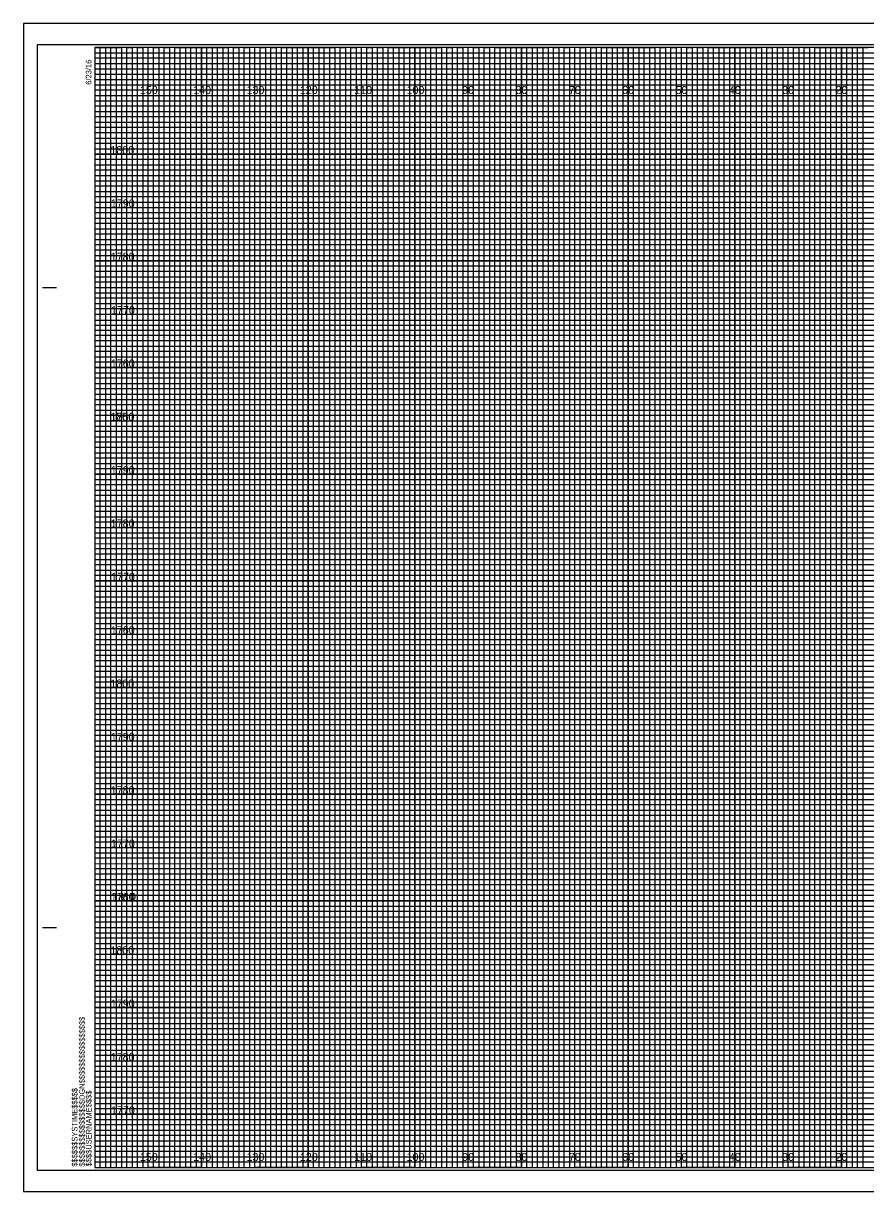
# Model space of a CAD drawing. Extents: x -13 to 323, y -5 to 874.
# Drawn here: x -13.4 to 144.5, y 435.5 to 654.5 of the extents above; entities that cross this region are included whole.
import ezdxf

# ---------------------------------------------------------------- set-up
doc = ezdxf.new("R2010")
doc.units = 0
for name, color, linetype in [('Prop XS Earthwork Shape', 7, 'Continuous'), ('Raster_Level_0', 7, 'Continuous'), ('Scratch_Level_1', 7, 'Continuous'), ('Scratch_Level_3', 7, 'Continuous'), ('Sheet Cross Section CELL', 7, 'Continuous'), ('Sheet Cross Section Grid Minor 1 CELL', 7, 'Continuous'), ('Sheet Cross Section Grid Minor 2 CELL', 7, 'Continuous'), ('Sheet Cutting Line CELL', 7, 'Continuous'), ('Sheet DOT Grid CELL', 7, 'Continuous'), ('Sheet Plot Border Inside CELL', 7, 'Continuous'), ('Sheet Plot Border Outside CELL', 7, 'Continuous')]:
    doc.layers.add(name, color=color, linetype=linetype)

msp = doc.modelspace()

# ---------------------------------------------------------------- linework, layer by layer
at = {"layer": 'Prop XS Earthwork Shape'}
for points in [[(0, 650), (5, 650), (5, 440), (15, 440), (15, 650), (25, 650), (25, 440), (35, 440), (35, 650), (45, 650), (45, 440), (55, 440), (55, 650), (65, 650), (65, 440), (75, 440), (75, 650), (85, 650), (85, 440), (95, 440), (95, 650), (105, 650), (105, 440), (115, 440), (115, 650), (125, 650), (125, 440), (135, 440), (135, 650), (145, 650)], [(0, 645), (275, 645)], [(0, 625), (320, 625), (320, 635), (0, 635)], [(0, 605), (320, 605), (320, 615), (0, 615)], [(0, 585), (320, 585), (320, 595), (0, 595)], [(0, 565), (320, 565), (320, 575), (0, 575)], [(0, 545), (320, 545), (320, 555), (0, 555)], [(0, 525), (320, 525), (320, 535), (0, 535)], [(0, 505), (320, 505), (320, 515), (0, 515)], [(0, 485), (320, 485), (320, 495), (0, 495)], [(0, 465), (320, 465), (320, 475), (0, 475)], [(0, 445), (320, 445), (320, 455), (0, 455)]]:
    msp.add_lwpolyline(points, dxfattribs=at)
at = {"layer": 'Scratch_Level_1'}
for p, q in [((10, 650), (0, 650)), ((10, 440), (10, 650)), ((30, 650), (20, 650)), ((20, 650), (20, 440)), ((30, 440), (30, 650)), ((50, 650), (40, 650)), ((40, 650), (40, 440)), ((50, 440), (50, 650)), ((70, 650), (60, 650)), ((60, 650), (60, 440)), ((70, 440), (70, 650)), ((90, 650), (80, 650)), ((80, 650), (80, 440)), ((90, 440), (90, 650)), ((110, 650), (100, 650)), ((100, 650), (100, 440)), ((110, 440), (110, 650)), ((130, 650), (120, 650)), ((120, 650), (120, 440)), ((130, 440), (130, 650)), ((150, 650), (140, 650)), ((140, 650), (140, 440)), ((20, 440), (10, 440)), ((40, 440), (30, 440)), ((60, 440), (50, 440)), ((80, 440), (70, 440)), ((100, 440), (90, 440)), ((120, 440), (110, 440)), ((140, 440), (130, 440))]:
    msp.add_line(p, q, dxfattribs=at)
for points in [[(0, 640), (320, 640), (320, 630), (0, 630)], [(0, 620), (320, 620), (320, 610), (0, 610)], [(0, 600), (320, 600), (320, 590), (0, 590)], [(0, 580), (320, 580), (320, 570), (0, 570)], [(0, 560), (320, 560), (320, 550), (0, 550)], [(0, 540), (320, 540), (320, 530), (0, 530)], [(0, 520), (320, 520), (320, 510), (0, 510)], [(0, 500), (320, 500), (320, 490), (0, 490)], [(0, 480), (320, 480), (320, 470), (0, 470)], [(0, 460), (320, 460), (320, 450), (0, 450)]]:
    msp.add_lwpolyline(points, dxfattribs=at)
at = {"layer": 'Sheet Cross Section CELL'}
for p, q in [((-9.8, 605), (-7.3, 605)), ((-9.7, 605), (-7.2, 605)), ((-9.8, 485), (-7.3, 485)), ((-9.7, 485), (-7.2, 485)), ((0, 440), (0, 440)), ((0, 440), (0, 440)), ((0, 440), (0, 440)), ((0, 440), (0, 440)), ((0, 440), (0, 440)), ((0, 440), (0, 440)), ((0, 440), (0, 440))]:
    msp.add_line(p, q, dxfattribs=at)
msp.add_lwpolyline([(320, 650), (0, 650), (0, 440), (320, 440)], close=True, dxfattribs=at)
at = {"layer": 'Sheet Cross Section Grid Minor 1 CELL'}
for p, q in [((0, 649), (260, 649)), ((260, 647.98), (0, 647.98)), ((0, 647.98), (0, 647)), ((0, 647), (260, 647)), ((260, 645.89), (0, 645.89)), ((0, 645.89), (0, 644)), ((0, 644), (320, 644))]:
    msp.add_line(p, q, dxfattribs=at)
for points in [[(0, 643), (270, 643), (320, 643), (320, 642), (0, 642)], [(0, 641), (320, 641), (320, 639), (0, 639)], [(0, 638), (320, 638), (320, 637), (0, 636.98)], [(0, 636), (320, 636), (320, 634), (0, 634)], [(0, 633), (320, 633), (320, 632), (0, 632)], [(0, 631), (320, 631), (320, 629), (0, 629)], [(0, 628), (320, 628), (320, 627), (0, 627)], [(0, 626), (320, 626), (320, 624), (0, 624)], [(0, 623), (320, 623), (320, 622), (0, 622)], [(0, 621), (320, 621), (320, 619), (0, 619)], [(0, 618), (320, 618), (320, 617), (0, 617)], [(0, 616), (320, 616), (320, 613.95), (320, 613), (320, 612), (0, 612)], [(0, 614), (320, 614), (320, 613), (0, 613)], [(0, 611), (320, 611), (320, 609), (0, 609.03)], [(0, 609.03), (320, 609), (320, 608), (0, 608)], [(0, 607), (320, 607), (320, 606), (0, 606)], [(0, 604), (320, 604), (320, 603), (0, 603)], [(0, 602), (320, 602), (320, 601), (0, 601)], [(-0.07, 598.89), (320, 598.89), (320, 597.88), (-0.07, 597.88)], [(0, 597), (320, 597), (320, 596), (0, 596)], [(0, 594), (320, 594), (320, 593), (0, 593)], [(0, 592), (320, 592), (320, 591), (0, 591)], [(0, 589), (320, 589), (320, 588), (0, 588)], [(0, 587), (320, 587), (320, 586), (0, 586)], [(0, 584), (320, 584), (320, 583), (0, 583)], [(0, 582), (320, 582), (320, 581), (0, 581)], [(0, 579), (320, 579), (319.99, 577.98), (0, 578)], [(0, 577), (320, 577), (320, 576), (0, 576)], [(0, 574), (320, 574), (320, 573), (0, 573)], [(0, 572), (320, 572), (320, 571), (0, 571)], [(0, 569), (320, 569), (320, 568), (0, 568)], [(0, 567), (320, 567), (320, 566), (0, 566)], [(0, 564), (320, 564), (320, 563), (0, 563)], [(0, 562), (320, 562), (320, 561), (0, 561)], [(0, 559), (320, 559), (320, 558), (0, 558)], [(0, 556.99), (320.07, 556.91), (320, 556), (0, 556)], [(0, 554), (320, 554), (320, 553), (0, 553)], [(0, 552), (320, 552), (320, 551), (0, 551)], [(0, 549), (320, 549), (320, 548), (0, 548)], [(0, 547), (320, 547), (320, 546), (0, 546)], [(0, 544), (320, 544), (320, 543), (0, 543)], [(0, 542), (320, 542), (320, 541), (0, 541)], [(0, 539), (320, 539), (320, 538), (0, 538)], [(0, 537), (320, 537), (320, 536), (0, 536)], [(0, 534), (320, 534), (320, 533), (0, 533)], [(0, 532), (320, 532), (320, 531), (0, 531)], [(0, 529), (320, 529), (320, 528), (0, 528)], [(0, 527), (320, 527), (320, 526), (0, 526)], [(0, 524), (320, 524), (320, 523), (0, 523)], [(0, 522), (320, 522), (320, 521), (0, 521)], [(0, 519), (320, 519), (319.99, 517.98), (0, 518)], [(0, 517), (320, 517), (320, 516), (0, 516)], [(0, 514), (320, 514), (320, 513), (0, 513)], [(0, 512), (320, 512), (320, 511), (0, 511)], [(0, 509), (320, 509), (320, 508), (0, 508)], [(0, 507), (320, 507), (320, 506), (0, 506)], [(0, 504), (320, 504), (320, 503), (0, 503)], [(0, 502), (320, 502), (320, 501), (0, 501)], [(0, 499), (320, 499), (320, 498), (0, 498)], [(0, 496.99), (320.07, 496.91), (320, 496), (0, 496)], [(0, 494), (320, 494), (320, 493), (0, 493)], [(0, 492), (320, 492), (320, 491), (0, 491)], [(0, 489), (320, 489), (320, 488), (0, 488)], [(0, 487), (320, 487), (320, 486), (0, 486)], [(0, 484), (320, 484), (320, 483), (0, 483)], [(0, 482), (320, 482), (320, 481), (0, 481)], [(0, 479), (320, 479), (320, 478), (0, 478)], [(0, 477), (320, 477), (320, 476), (0, 476)], [(0, 474), (320, 474), (320, 473), (0, 473)], [(0, 472), (320, 472), (320, 471), (0, 471)], [(0, 469), (320, 469), (320, 468), (0, 468)], [(0, 467), (320, 467), (320, 466), (0, 466)], [(0, 464), (320, 464), (320, 463), (0, 463)], [(0, 462), (320, 462), (320, 461), (0, 461)], [(0, 459), (320, 459), (320, 458), (0, 458)], [(0, 457), (320, 457), (320, 456), (0, 456)], [(0, 454), (320, 454), (320, 453), (0, 453)], [(0, 452), (320, 452), (320, 451), (0, 451)], [(0, 449), (320, 449), (320, 448), (0, 448)], [(0, 447), (320, 447), (320, 446), (0, 446)], [(0, 444), (320, 444), (320, 443), (0, 443)], [(0, 442), (320, 442), (320, 441), (0, 441)]]:
    msp.add_lwpolyline(points, dxfattribs=at)
at = {"layer": 'Sheet Cross Section Grid Minor 2 CELL'}
for points in [[(0, 440), (1, 440), (1, 650), (2, 650), (2, 440)], [(2, 440), (3, 440), (3, 650), (4, 650), (4, 440)], [(5, 440), (6, 440), (6, 650), (7, 650), (7, 440)], [(7, 440), (8, 440), (8, 650), (9, 650), (9, 440)], [(10, 440), (11, 440), (11, 650), (12, 650), (12, 440)], [(12, 440), (13, 440), (13, 650), (14, 650), (14, 440)], [(15, 440), (16, 440), (16, 650), (17, 650), (17, 440)], [(17, 440), (18, 440), (18, 650), (19, 650), (19, 440)], [(20, 440), (21, 440), (21, 650), (22, 650), (22, 440)], [(22, 440), (23, 440), (23, 650), (24, 650), (24, 440)], [(25, 440), (26, 440), (26, 650), (27, 650), (27, 440)], [(27, 440), (28, 440), (28, 650), (29, 650), (29, 440)], [(30, 440), (31, 440), (31, 650), (32, 650), (32, 440)], [(32, 440), (33, 440), (33, 650), (34, 650), (34, 440)], [(35, 440), (36, 440), (36, 650), (37, 650), (37, 440)], [(37, 440), (38, 440), (38, 650), (39, 650), (39, 440)], [(40, 440), (41, 440), (41, 650), (42, 650), (42, 440)], [(42, 440), (43, 440), (43, 650), (44, 650), (44, 440)], [(45, 440), (46, 440), (46, 650), (47, 650), (47, 440)], [(47, 440), (48, 440), (48, 650), (49, 650), (49, 440)], [(50, 440), (51, 440), (51, 650), (52, 650), (52, 440)], [(52, 440), (53, 440), (53, 650), (54, 650), (54, 440)], [(55, 440), (56, 440), (56, 650), (57, 650), (57, 440)], [(57, 440), (58, 440), (58, 650), (59, 650), (59, 440)], [(60, 440), (61, 440), (61, 650), (62, 650), (62, 440)], [(62, 440), (63, 440), (63, 650), (64, 650), (64, 440)], [(65, 440), (66, 440), (66, 650), (67, 650), (67, 440)], [(67, 440), (68, 440), (68, 650), (69, 650), (69, 440)], [(70, 440), (71, 440), (71, 650), (72, 650), (72, 440)], [(72, 440), (73, 440), (73, 650), (74, 650), (74, 440)], [(75, 440), (76, 440), (76, 650), (77, 650), (77, 440)], [(77, 440), (78, 440), (78, 650), (79, 650), (79, 440)], [(80, 440), (81, 440), (81, 650), (82, 650), (82, 440)], [(82, 440), (83, 440), (83, 650), (84, 650), (84, 440)], [(85, 440), (86, 440), (86, 650), (87, 650), (87, 440)], [(87, 440), (88, 440), (88, 650), (89, 650), (89, 440)], [(90, 440), (91, 440), (91, 650), (92, 650), (92, 440)], [(92, 440), (93, 440), (93, 650), (94, 650), (94, 440)], [(95, 440), (96, 440), (96, 650), (97, 650), (97, 440)], [(97, 440), (98, 440), (98, 650), (99, 650), (99, 440)], [(100, 440), (101, 440), (101, 650), (102, 650), (102, 440)], [(102, 440), (103, 440), (103, 650), (104, 650), (104, 440)], [(105, 440), (106, 440), (106, 650), (107, 650), (107, 440)], [(107, 440), (108, 440), (108, 650), (109, 650), (109, 440)], [(110, 440), (111, 440), (111, 650), (112, 650), (112, 440)], [(112, 440), (113, 440), (113, 650), (114, 650), (114, 440)], [(115, 440), (116, 440), (116, 650), (117, 650), (117, 440)], [(117, 440), (118, 440), (118, 650), (119, 650), (119, 440)], [(120, 440), (121, 440), (121, 650), (122, 650), (122, 440)], [(122, 440), (123, 440), (123, 650), (124, 650), (124, 440)], [(125, 440), (126, 440), (126, 650), (127, 650), (127, 440)], [(127, 440), (128, 440), (128, 650), (129, 650), (129, 440)], [(130, 440), (131, 440), (131, 650), (132, 650), (132, 440)], [(132, 440), (133, 440), (133, 650), (134, 650), (134, 440)], [(135, 440), (136, 440), (136, 650), (137, 650), (137, 440)], [(137, 440), (138, 440), (138, 650), (139, 650), (139, 440)], [(140, 440), (141, 440), (141, 650), (142, 650), (142, 440)], [(142, 440), (143, 440), (143, 650), (144, 650), (144, 440)]]:
    msp.add_lwpolyline(points, dxfattribs=at)
at = {"layer": 'Sheet Cutting Line CELL'}
for p, q in [((323.3, 654.5), (-13.4, 654.5)), ((-13.4, 654.5), (-13.4, 435.5)), ((-13.4, 435.5), (323.3, 435.5))]:
    msp.add_line(p, q, dxfattribs=at)
at = {"layer": 'Sheet DOT Grid CELL'}
for p, q in [((10, 440), (10, 650)), ((20, 440), (20, 650)), ((30, 440), (30, 650)), ((40, 440), (40, 650)), ((50, 440), (50, 650)), ((60, 440), (60, 650)), ((70, 440), (70, 650)), ((80, 440), (80, 650)), ((90, 440), (90, 650)), ((100, 440), (100, 650)), ((110, 440), (110, 650)), ((120, 440), (120, 650)), ((130, 440), (130, 650)), ((140, 440), (140, 650)), ((0, 640), (320, 640)), ((0, 630), (320, 630)), ((0, 620), (320, 620)), ((0, 610), (320, 610)), ((0, 600), (320, 600)), ((0, 590), (320, 590)), ((0, 580), (320, 580)), ((0, 570), (320, 570)), ((0, 560), (320, 560)), ((0, 550), (320, 550)), ((0, 540), (320, 540)), ((0, 530), (320, 530)), ((0, 520), (320, 520)), ((0, 510), (320, 510)), ((0, 500), (320, 500)), ((0, 490), (320, 490)), ((0, 480), (320, 480)), ((0, 470), (320, 470)), ((0, 460), (320, 460)), ((0, 450), (320, 450))]:
    msp.add_line(p, q, dxfattribs=at)
at = {"layer": 'Sheet Plot Border Inside CELL'}
msp.add_lwpolyline([(-10.8, 439.5), (322.4, 439.5), (322.4, 650.5), (-10.8, 650.5)], close=True, dxfattribs=at)
at = {"layer": 'Sheet Plot Border Outside CELL'}
msp.add_lwpolyline([(-13.4, 435.5), (323.3, 435.5), (323.3, 654.5), (-13.4, 654.5)], close=True, dxfattribs=at)

# ---------------------------------------------------------------- texts
at = {"layer": 'Raster_Level_0'}
for s, p in [('150', (8.44, 641.25)), ('140', (18.44, 641.25)), ('130', (28.44, 641.25)), ('120', (38.44, 641.25)), ('110', (48.62, 641.25)), ('100', (58.44, 641.25)), ('90', (68.86, 641.25)), ('80', (78.86, 641.25)), ('70', (88.86, 641.25)), ('60', (98.86, 641.25)), ('50', (108.86, 641.25)), ('40', (118.86, 641.25)), ('30', (128.86, 641.25)), ('20', (138.86, 641.25)), ('150', (8.44, 441.25)), ('140', (18.44, 441.25)), ('130', (28.44, 441.25)), ('120', (38.44, 441.25)), ('110', (48.62, 441.25)), ('100', (58.44, 441.25)), ('90', (68.86, 441.25)), ('80', (78.86, 441.25)), ('70', (88.86, 441.25)), ('60', (98.86, 441.25)), ('50', (108.86, 441.25)), ('40', (118.86, 441.25)), ('30', (128.86, 441.25)), ('20', (138.86, 441.25))]:
    msp.add_text(s, height=1.5, dxfattribs=at).set_placement(p)
at = {"layer": 'Scratch_Level_3'}
for s, p in [('1800', (2.92, 630)), ('1790', (3, 620)), ('1780', (2.98, 610)), ('1770', (3.04, 600)), ('1760', (3, 590)), ('1800', (2.92, 580)), ('1750', (2.96, 580)), ('1790', (3, 570)), ('1780', (2.98, 560)), ('1770', (3.04, 550)), ('1760', (3, 540)), ('1800', (2.92, 530)), ('1790', (3, 520)), ('1780', (2.98, 510)), ('1770', (3.04, 500)), ('1760', (3, 490)), ('1810', (3.25, 490)), ('1800', (2.92, 480)), ('1790', (3, 470)), ('1780', (2.98, 460)), ('1770', (3.04, 450))]:
    msp.add_text(s, height=1.5, dxfattribs=at).set_placement(p)
at = {"layer": 'Sheet Cross Section CELL'}
for s, p in [('6/23/16', (-0.65, 643)), ('$$$$$$$$$$$$$$$$DGN$$$$$$$$$$$$$$$$', (-1.88, 440.18)), ('$$$$$$SYSTIME$$$$$', (-3.26, 440.18)), ('$$$$USERNAME$$$$', (-0.62, 440.23))]:
    msp.add_text(s, height=1.05, rotation=90, dxfattribs=at).set_placement(p)

doc.saveas('drawing.dxf')
